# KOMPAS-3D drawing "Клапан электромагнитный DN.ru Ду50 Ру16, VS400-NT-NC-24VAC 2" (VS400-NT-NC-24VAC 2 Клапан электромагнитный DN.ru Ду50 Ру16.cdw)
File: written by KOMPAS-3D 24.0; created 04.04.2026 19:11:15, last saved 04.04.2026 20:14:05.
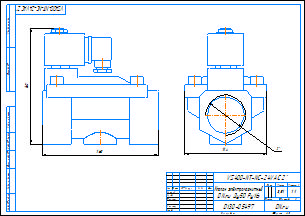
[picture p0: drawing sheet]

Document properties: c3d_UniqueCompID: ef56311e-7521-43dc-8291-0e6108b3d81d; Обозначение: VS400-ET-NC-220VAC 2; Наименование: Клапан электромагнитный DN.ru Ду50 Ру16; Автор: artio; Класс точности: c; Знак неуказанной шероховатости: Шероховатость не задана; Рассекать на разрезах: Да; c3d_UniqueCompID: ef56311e-7521-43dc-8291-0e6108b3d81d; Обозначение: VS400-ET-NC-220VAC 1; Наименование: Клапан электромагнитный DN.ru Ду25 Ру16; Автор: artio; Класс точности: c; Знак неуказанной шероховатости: Шероховатость не задана; Рассекать на разрезах: Да; c3d_UniqueCompID: ef56311e-7521-43dc-8291-0e6108b3d81d; Обозначение: VS400-ET-NC-220VAC 1-2; Наименование: Клапан электромагнитный DN.ru Ду15 Ру16; Автор: artio; Класс точности: c; Знак неуказанной шероховатости: Шероховатость не задана; Рассекать на разрезах: Да; c3d_UniqueCompID: ef56311e-7521-43dc-8291-0e6108b3d81d; Обозначение: VS400-ET-NC-220VAC 3-4; Наименование: Клапан электромагнитный DN.ru Ду20 Ру16; Автор: artio; Класс точности: c; Знак неуказанной шероховатости: Шероховатость не задана; Рассекать на разрезах: Да; c3d_UniqueCompID: ef56311e-7521-43dc-8291-0e6108b3d81d; Обозначение: VS400-ET-NC-220VAC 1 1-4; Наименование: Клапан электромагнитный DN.ru Ду32 Ру16; Автор: artio; Класс точности: c; Знак неуказанной шероховатости: Шероховатость не задана; Рассекать на разрезах: Да; c3d_UniqueCompID: ef56311e-7521-43dc-8291-0e6108b3d81d; Обозначение: VS400-ET-NC-220VAC 3-8; Наименование: Клапан электромагнитный DN.ru Ду10 Ру16; Автор: artio; Класс точности: c; Знак неуказанной шероховатости: Шероховатость не задана; Рассекать на разрезах: Да; c3d_UniqueCompID: ef56311e-7521-43dc-8291-0e6108b3d81d; Обозначение: VS400-ET-NC-220VAC 1 1-2; Наименование: Клапан электромагнитный DN.ru Ду40 Ру16; Автор: artio; Класс точности: c; Знак неуказанной шероховатости: Шероховатость не задана; Рассекать на разрезах: Да; Автор: artio; Форматы листов документа: A3; Полное имя файла: VS400-NT-NC-24VAC 2 Клапан электромагнитный DN.ru Ду50 Ру16.m3d; Масса: 3.509; Наименование: Клапан электромагнитный DN.ru Ду50 Ру16; Количество листов документа: 1; Примечание: D130-05497

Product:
- Body: Тело 1  | qty 1
    Масса: 7.119215
- Part/product: Клапан электромагнитный DN.ru Ду50 Ру16  | designation VS400-NT-NC-24VAC 2
    Масса: 3.509
    Раздел спецификации: Прочие изделия
    Примечание: D130-05497
    additional columns: ef56311e-7521-43dc-8291-0e6108b3d81d; VS400-ET-NC-220VAC 2; artio; c; Шероховатость не задана; Да

Views: Вид 1, Спереди
Referenced files in C:\Users\artio\OneDrive\Рабочий стол\Клапан электромагнитный DN.ru\VS400-ET-NC\VS400-ET-NC-24VDC\: VS400-ET-NC-24VDC 3-8 Клапан электромагнитный DN.ru Ду10 Ру16.m3d
Referenced files in C:\Users\artio\OneDrive\Рабочий стол\Клапан электромагнитный DN.ru\VS400-NT-NC\VS400-NT-NC-24VAC\: VS400-NT-NC-24VAC 2 Клапан электромагнитный DN.ru Ду50 Ру16.m3d
Referenced files in C:\Users\artio\OneDrive\Рабочий стол\Клапан электромагнитный DN.ru\VS400-ET-NC\: VS400-ET-NC-24VDC 3-8 Клапан электромагнитный DN.ru Ду10 Ру16.cdw
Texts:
  VS400-NT-NC-24VAC 2
  Клапан электромагнитный
  DN.ru Ду50 Ру16
  VS400-NT-NC-24VAC 2"
  VS400-NT-NC-24VAC 2"-
  Клапан электромагнитный DN.ru Ду50 Ру16
  VS400-NT-NC-24VAC 2 Клапан электромагнитный DN.ru Ду50 Ру16
Dimensions and other numbers on the sheet: 0; 3; 2; 4; 114; 1:1; 1; 3,51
